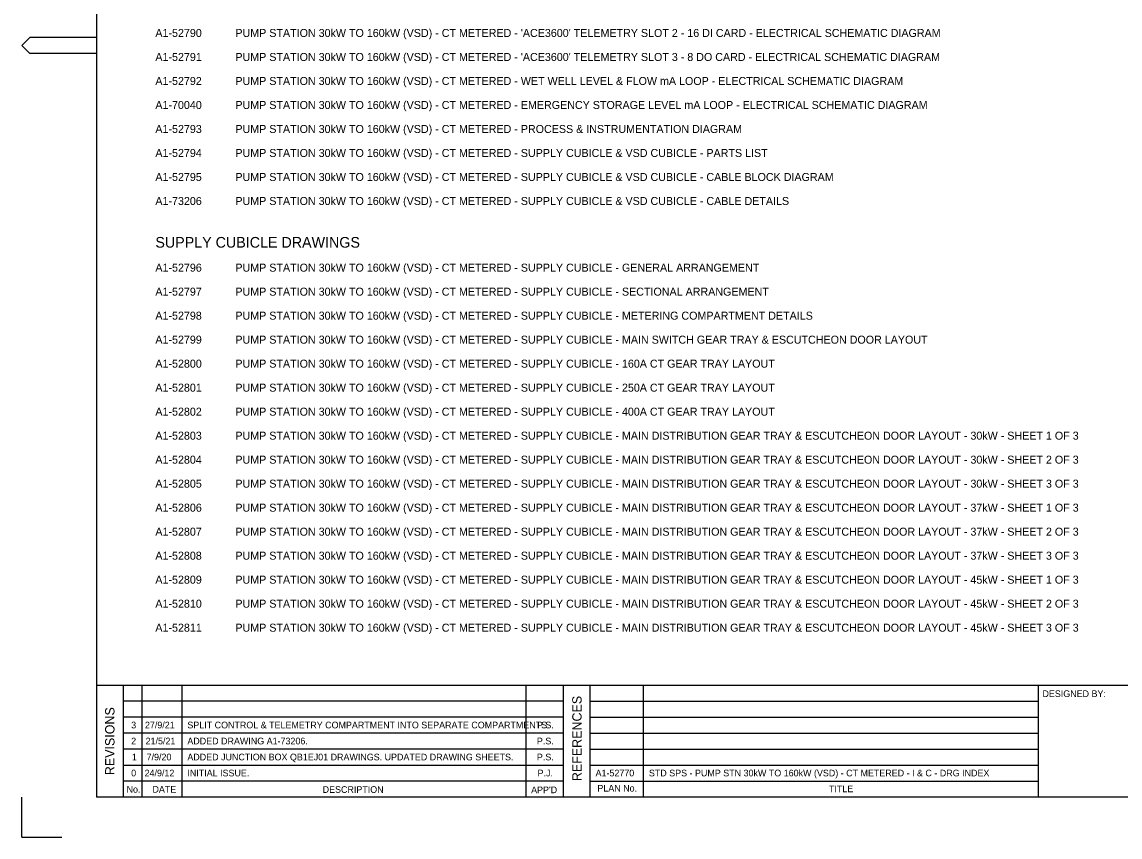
# Model space of a CAD drawing. Extents: x 0 to 841, y 0 to 594.
# Drawn here: x 0 to 411.6, y 0 to 305.6 of the extents above; entities that cross this region are included whole.
import ezdxf

# ---------------------------------------------------------------- set-up
doc = ezdxf.new("R2010")
doc.units = 0
doc.layers.add('A1BORDER', color=7, linetype='Continuous')
doc.layers.add('Level 1', color=7, linetype='Continuous')

msp = doc.modelspace()

# ---------------------------------------------------------------- linework, layer by layer
at = {"layer": 'A1BORDER'}
for p, q in [((28, 581), (28, 15)), ((3, 299.76), (0, 296.76)), ((3, 293.76), (0, 296.76)), ((28, 299.76), (3, 299.76)), ((28, 293.76), (3, 293.76)), ((28, 57), (829, 57)), ((38, 15), (38, 57)), ((45, 15), (45, 57)), ((60, 15), (60, 57)), ((189, 15), (189, 57)), ((203, 15), (203, 57)), ((213, 15), (213, 57)), ((233, 15), (233, 57)), ((381, 15), (381, 57)), ((203, 51), (38, 51)), ((213, 51), (381, 51)), ((203, 45), (38, 45)), ((213, 45), (381, 45)), ((203, 39), (38, 39)), ((213, 39), (381, 39)), ((203, 33), (38, 33)), ((213, 33), (381, 33)), ((38, 27), (203, 27)), ((213, 27), (381, 27)), ((203, 21), (38, 21)), ((213, 21), (381, 21)), ((0, 0), (0, 15)), ((829, 15), (28, 15)), ((0, 0), (15, 0))]:
    msp.add_line(p, q, dxfattribs=at)

# ---------------------------------------------------------------- texts
for s, height, p in [('DESIGNED BY:', 2.5, (382.5, 52.5)), ('No.', 2.5, (39.21, 16.65)), ('DATE', 2.5, (48.92, 16.65)), ('DESCRIPTION', 2.50002, (112.71, 16.57)), ("APP'D", 2.5, (190.85, 16.44)), ('PLAN No.', 2.5, (215.69, 17.06)), ('TITLE', 2.5, (302.5, 16.81))]:
    msp.add_text(s, height=height, dxfattribs=at).set_placement(p)
for s, p in [('REFERENCES', (209.76, 20.96)), ('REVISIONS', (34.68, 23.2))]:
    msp.add_text(s, height=3.5, rotation=90, dxfattribs=at).set_placement(p)
at = {"layer": 'Level 1'}
for s, height, p in [('A1-52790', 3, (50, 300)), ("PUMP STATION 30kW TO 160kW (VSD) - CT METERED - 'ACE3600' TELEMETRY SLOT 2 - 16 DI CARD - ELECTRICAL SCHEMATIC DIAGRAM", 3, (80, 300)), ('A1-52791', 3, (50, 291)), ("PUMP STATION 30kW TO 160kW (VSD) - CT METERED - 'ACE3600' TELEMETRY SLOT 3 - 8 DO CARD - ELECTRICAL SCHEMATIC DIAGRAM", 3, (80, 291)), ('A1-52792', 3, (50, 282)), ('PUMP STATION 30kW TO 160kW (VSD) - CT METERED - WET WELL LEVEL & FLOW mA LOOP - ELECTRICAL SCHEMATIC DIAGRAM', 3, (80, 282)), ('A1-70040', 3, (50, 273)), ('PUMP STATION 30kW TO 160kW (VSD) - CT METERED - EMERGENCY STORAGE LEVEL mA LOOP - ELECTRICAL SCHEMATIC DIAGRAM', 3, (80, 273)), ('A1-52793', 3, (50, 264)), ('PUMP STATION 30kW TO 160kW (VSD) - CT METERED - PROCESS & INSTRUMENTATION DIAGRAM', 3, (80, 264)), ('A1-52794', 3, (50, 255)), ('PUMP STATION 30kW TO 160kW (VSD) - CT METERED - SUPPLY CUBICLE & VSD CUBICLE - PARTS LIST', 3, (80, 255)), ('A1-52795', 3, (50, 246)), ('PUMP STATION 30kW TO 160kW (VSD) - CT METERED - SUPPLY CUBICLE & VSD CUBICLE - CABLE BLOCK DIAGRAM', 3, (80, 246)), ('A1-73206', 3, (50, 237)), ('PUMP STATION 30kW TO 160kW (VSD) - CT METERED - SUPPLY CUBICLE & VSD CUBICLE - CABLE DETAILS', 3, (80, 237)), ('SUPPLY CUBICLE DRAWINGS', 4, (50, 221)), ('A1-52796', 3, (50, 212)), ('PUMP STATION 30kW TO 160kW (VSD) - CT METERED - SUPPLY CUBICLE - GENERAL ARRANGEMENT', 3, (80, 212)), ('A1-52797', 3, (50, 203)), ('PUMP STATION 30kW TO 160kW (VSD) - CT METERED - SUPPLY CUBICLE - SECTIONAL ARRANGEMENT', 3, (80, 203)), ('A1-52798', 3, (50, 194)), ('PUMP STATION 30kW TO 160kW (VSD) - CT METERED - SUPPLY CUBICLE - METERING COMPARTMENT DETAILS', 3, (80, 194)), ('A1-52799', 3, (50, 185)), ('PUMP STATION 30kW TO 160kW (VSD) - CT METERED - SUPPLY CUBICLE - MAIN SWITCH GEAR TRAY & ESCUTCHEON DOOR LAYOUT', 3, (80, 185)), ('A1-52800', 3, (50, 176)), ('PUMP STATION 30kW TO 160kW (VSD) - CT METERED - SUPPLY CUBICLE - 160A CT GEAR TRAY LAYOUT', 3, (80, 176)), ('A1-52801', 3, (50, 167)), ('PUMP STATION 30kW TO 160kW (VSD) - CT METERED - SUPPLY CUBICLE - 250A CT GEAR TRAY LAYOUT', 3, (80, 167)), ('A1-52802', 3, (50, 158)), ('PUMP STATION 30kW TO 160kW (VSD) - CT METERED - SUPPLY CUBICLE - 400A CT GEAR TRAY LAYOUT', 3, (80, 158)), ('A1-52803', 3, (50, 149)), ('PUMP STATION 30kW TO 160kW (VSD) - CT METERED - SUPPLY CUBICLE - MAIN DISTRIBUTION GEAR TRAY & ESCUTCHEON DOOR LAYOUT - 30kW - SHEET 1 OF 3', 3, (80, 149)), ('A1-52804', 3, (50, 140)), ('PUMP STATION 30kW TO 160kW (VSD) - CT METERED - SUPPLY CUBICLE - MAIN DISTRIBUTION GEAR TRAY & ESCUTCHEON DOOR LAYOUT - 30kW - SHEET 2 OF 3', 3, (80, 140)), ('A1-52805', 3, (50, 131)), ('PUMP STATION 30kW TO 160kW (VSD) - CT METERED - SUPPLY CUBICLE - MAIN DISTRIBUTION GEAR TRAY & ESCUTCHEON DOOR LAYOUT - 30kW - SHEET 3 OF 3', 3, (80, 131)), ('A1-52806', 3, (50, 122)), ('PUMP STATION 30kW TO 160kW (VSD) - CT METERED - SUPPLY CUBICLE - MAIN DISTRIBUTION GEAR TRAY & ESCUTCHEON DOOR LAYOUT - 37kW - SHEET 1 OF 3', 3, (80, 122)), ('A1-52807', 3, (50, 113)), ('PUMP STATION 30kW TO 160kW (VSD) - CT METERED - SUPPLY CUBICLE - MAIN DISTRIBUTION GEAR TRAY & ESCUTCHEON DOOR LAYOUT - 37kW - SHEET 2 OF 3', 3, (80, 113)), ('A1-52808', 3, (50, 104)), ('PUMP STATION 30kW TO 160kW (VSD) - CT METERED - SUPPLY CUBICLE - MAIN DISTRIBUTION GEAR TRAY & ESCUTCHEON DOOR LAYOUT - 37kW - SHEET 3 OF 3', 3, (80, 104)), ('A1-52809', 3, (50, 95)), ('PUMP STATION 30kW TO 160kW (VSD) - CT METERED - SUPPLY CUBICLE - MAIN DISTRIBUTION GEAR TRAY & ESCUTCHEON DOOR LAYOUT - 45kW - SHEET 1 OF 3', 3, (80, 95)), ('A1-52810', 3, (50, 86)), ('PUMP STATION 30kW TO 160kW (VSD) - CT METERED - SUPPLY CUBICLE - MAIN DISTRIBUTION GEAR TRAY & ESCUTCHEON DOOR LAYOUT - 45kW - SHEET 2 OF 3', 3, (80, 86)), ('A1-52811', 3, (50, 77)), ('PUMP STATION 30kW TO 160kW (VSD) - CT METERED - SUPPLY CUBICLE - MAIN DISTRIBUTION GEAR TRAY & ESCUTCHEON DOOR LAYOUT - 45kW - SHEET 3 OF 3', 3, (80, 77)), ('3', 2.5, (40.94, 40.75)), ('27/9/21', 2.5, (46.094, 40.75)), ('SPLIT CONTROL & TELEMETRY COMPARTMENT INTO SEPARATE COMPARTMENTS.', 2.50002, (62, 40.75)), ('P.S.', 2.5, (193.015, 40.75)), ('2', 2.5, (40.94, 34.75)), ('21/5/21', 2.5, (46.343, 34.75)), ('ADDED DRAWING A1-73206.', 2.50002, (62, 34.75)), ('P.S.', 2.5, (193.015, 34.75)), ('1', 2.5, (41.189, 28.75)), ('7/9/20', 2.5, (46.716, 28.75)), ('ADDED JUNCTION BOX QB1EJ01 DRAWINGS. UPDATED DRAWING SHEETS.', 2.50002, (62, 28.75)), ('P.S.', 2.5, (193.015, 28.75)), ('0', 2.5, (40.94, 22.75)), ('24/9/12', 2.5, (45.969, 22.75)), ('INITIAL ISSUE.', 2.50002, (62, 22.75)), ('P.J.', 2.5, (193.265, 22.75)), ('A1-52770', 2.5, (215, 22.75)), ('STD SPS - PUMP STN 30kW TO 160kW (VSD) - CT METERED - I & C - DRG INDEX', 2.50002, (235, 22.75))]:
    msp.add_text(s, height=height, dxfattribs=at).set_placement(p)

doc.saveas('drawing.dxf')
